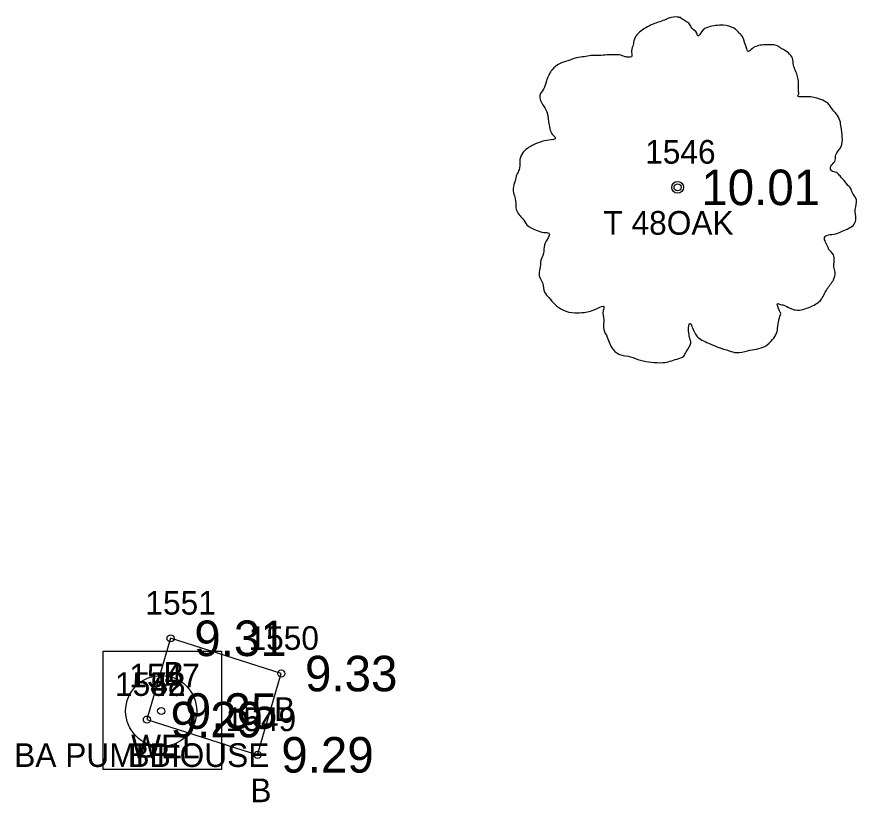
# Model space of a CAD drawing. Extents: x 2608598 to 2610682, y 641451 to 643526.
# Drawn here: x 2609098.39 to 2609133.87, y 643248.82 to 643281.98 of the extents above; entities that cross this region are included whole.
import ezdxf

# ---------------------------------------------------------------- set-up
doc = ezdxf.new("R2010")
doc.units = 0
for name, color, linetype in [('RD_EX_Bldg', 7, 'Continuous'), ('RD_EX_Bldg_txCode', 7, 'Continuous'), ('RD_EX_BldgApp_txCode', 7, 'Continuous'), ('RD_EX_SU_H2O', 7, 'Continuous'), ('RD_EX_TX_Bldg_ELEV', 7, 'Continuous'), ('RD_EX_TX_BldgApp_ELEV', 7, 'Continuous'), ('RD_EX_TX_VEG_ELEV', 7, 'Continuous'), ('RD_EX_VEG', 7, 'Continuous'), ('RD_EX_VEG_txCode', 7, 'Continuous'), ('RD_SMD_Locator', 7, 'Continuous')]:
    doc.layers.add(name, color=color, linetype=linetype)

msp = doc.modelspace()

# ---------------------------------------------------------------- linework, layer by layer
at = {"layer": 'RD_EX_Bldg'}
msp.add_lwpolyline([(2609103.878, 643252.305), (2609108.553, 643250.817), (2609109.553, 643254.249), (2609104.878, 643255.737), (2609103.878, 643252.305)], dxfattribs=at)
at = {"layer": 'RD_EX_BldgApp_txCode'}
msp.add_circle((2609104.482, 643252.665), 0.15, dxfattribs=at)
at = {"layer": 'RD_EX_SU_H2O'}
msp.add_lwpolyline([(2609102.029, 643250.193), (2609102.029, 643255.193), (2609107.029, 643255.193), (2609107.029, 643250.193)], close=True, dxfattribs=at)
msp.add_circle((2609104.482, 643252.665), 1.5, dxfattribs=at)
at = {"layer": 'RD_EX_VEG'}
for centre, radius in [((2609126.286, 643274.778), 0.25), ((2609126.273, 643274.759), 0.0001)]:
    msp.add_circle(centre, radius, dxfattribs=at)
for points in [[(2609126.418, 643281.945), (2609126.118, 643281.97), (2609125.793, 643281.87), (2609125.543, 643281.77), (2609125.318, 643281.695), (2609125.094, 643281.595), (2609124.794, 643281.42), (2609124.569, 643281.22), (2609124.444, 643280.97), (2609124.394, 643280.745), (2609124.344, 643280.471), (2609124.344, 643280.296), (2609124.219, 643280.271), (2609124.069, 643280.296), (2609123.819, 643280.371), (2609123.569, 643280.371), (2609123.319, 643280.371), (2609122.969, 643280.346), (2609122.62, 643280.346), (2609122.345, 643280.296), (2609122.02, 643280.246), (2609121.645, 643280.121), (2609121.295, 643279.996), (2609120.995, 643279.746), (2609120.745, 643279.271), (2609120.62, 643278.921), (2609120.471, 643278.671), (2609120.62, 643278.222), (2609120.795, 643277.872), (2609120.82, 643277.672), (2609120.895, 643277.247), (2609120.995, 643277.022), (2609121.12, 643276.822), (2609121.045, 643276.797), (2609120.67, 643276.747), (2609120.371, 643276.647), (2609119.946, 643276.422), (2609119.721, 643276.197), (2609119.621, 643275.872), (2609119.596, 643275.523), (2609119.496, 643275.323), (2609119.421, 643275.048), (2609119.396, 643274.973), (2609119.346, 643274.648), (2609119.446, 643274.198), (2609119.471, 643273.848), (2609119.596, 643273.623), (2609119.746, 643273.449), (2609119.921, 643273.199), (2609120.321, 643272.974), (2609120.645, 643272.874), (2609120.845, 643272.849), (2609120.67, 643272.349), (2609120.62, 643271.999), (2609120.496, 643271.599), (2609120.496, 643271.524), (2609120.446, 643271.05), (2609120.595, 643270.725), (2609120.67, 643270.35), (2609120.845, 643270.125), (2609121.12, 643269.825), (2609121.445, 643269.6), (2609121.945, 643269.475), (2609122.345, 643269.5), (2609122.92, 643269.675), (2609123.169, 643269.75), (2609123.144, 643269.575), (2609123.169, 643269.2), (2609123.169, 643268.776), (2609123.319, 643268.451), (2609123.419, 643268.176), (2609123.569, 643267.926), (2609123.894, 643267.701), (2609124.294, 643267.626), (2609124.719, 643267.476), (2609125.169, 643267.401), (2609125.668, 643267.376), (2609126.268, 643267.526), (2609126.543, 643267.651), (2609126.643, 643267.826), (2609126.843, 643268.201), (2609126.793, 643268.426), (2609126.818, 643269.026), (2609126.918, 643268.851), (2609127.093, 643268.501), (2609127.592, 643268.201), (2609127.992, 643268.026), (2609128.467, 643267.876), (2609128.767, 643267.801), (2609129.242, 643267.876), (2609129.617, 643267.951), (2609129.991, 643268.076), (2609130.291, 643268.351), (2609130.466, 643268.626), (2609130.516, 643268.901), (2609130.591, 643269.275), (2609130.641, 643269.45)], [(2609130.641, 643269.45), (2609130.566, 643269.625), (2609130.516, 643269.875), (2609130.591, 643269.85), (2609130.766, 643269.8), (2609131.041, 643269.675), (2609131.266, 643269.6), (2609131.591, 643269.625), (2609131.866, 643269.725), (2609132.315, 643270), (2609132.59, 643270.475), (2609132.865, 643270.875), (2609132.94, 643271.2), (2609132.89, 643271.424), (2609132.865, 643271.924), (2609132.665, 643272.174), (2609132.615, 643272.299), (2609132.515, 643272.699), (2609132.59, 643272.749), (2609132.865, 643272.799), (2609133.24, 643272.924), (2609133.515, 643273.049), (2609133.74, 643273.224), (2609133.815, 643273.449), (2609133.79, 643273.848), (2609133.84, 643274.248), (2609133.765, 643274.398), (2609133.665, 643274.548), (2609133.59, 643274.748), (2609133.44, 643274.898), (2609133.34, 643275.048), (2609133.24, 643275.148), (2609133.115, 643275.298), (2609132.94, 643275.423), (2609132.79, 643275.473), (2609132.74, 643275.623), (2609132.89, 643275.823), (2609132.94, 643275.922), (2609132.965, 643276.147), (2609133.19, 643276.497), (2609133.24, 643276.897), (2609133.19, 643277.322), (2609133.14, 643277.597), (2609132.99, 643277.872), (2609132.79, 643278.122), (2609132.665, 643278.296), (2609132.49, 643278.421), (2609132.165, 643278.546), (2609131.916, 643278.596), (2609131.566, 643278.596), (2609131.366, 643278.646), (2609131.391, 643278.696), (2609131.391, 643278.846), (2609131.391, 643279.121), (2609131.316, 643279.571), (2609131.166, 643280.071), (2609131.166, 643280.096), (2609131.066, 643280.346), (2609130.841, 643280.545), (2609130.666, 643280.645), (2609130.466, 643280.77), (2609130.216, 643280.795), (2609129.916, 643280.795), (2609129.642, 643280.745), (2609129.442, 643280.645), (2609129.267, 643280.52), (2609129.192, 643280.67), (2609129.092, 643280.97), (2609129.042, 643281.12), (2609128.892, 643281.295), (2609128.667, 643281.495), (2609128.217, 643281.62), (2609127.592, 643281.545), (2609127.293, 643281.345), (2609127.143, 643281.17), (2609127.093, 643281.295), (2609126.893, 643281.495), (2609126.793, 643281.67), (2609126.618, 643281.795), (2609126.468, 643281.895), (2609126.368, 643281.945)]]:
    msp.add_spline(points, degree=3, dxfattribs=at)
at = {"layer": 'RD_SMD_Locator'}
for centre in [(2609126.286, 643274.778), (2609104.878, 643255.737), (2609109.553, 643254.249), (2609103.878, 643252.305), (2609103.878, 643252.305), (2609108.553, 643250.817)]:
    msp.add_circle(centre, 0.15, dxfattribs=at)

# ---------------------------------------------------------------- texts
at = {"layer": 'RD_EX_Bldg_txCode'}
for s, p in [('1551', (2609103.815, 643256.737)), ('1550', (2609108.167, 643255.249)), ('B', (2609104.571, 643253.737)), ('1548', (2609102.532, 643253.305)), ('1552', (2609102.532, 643253.305)), ('B', (2609109.246, 643252.249)), ('1549', (2609107.206, 643251.817)), ('BA PUMPHOUSE', (2609098.276, 643250.305)), ('BB', (2609103.099, 643250.305)), ('B', (2609108.246, 643248.817))]:
    msp.add_text(s, height=1, dxfattribs=at).set_placement(p)
at = {"layer": 'RD_EX_BldgApp_txCode'}
for s, p in [('1547', (2609103.136, 643253.665)), ('WEL', (2609103.214, 643250.665))]:
    msp.add_text(s, height=1, dxfattribs=at).set_placement(p)
at = {"layer": 'RD_EX_TX_Bldg_ELEV'}
for s, p in [('9.31', (2609105.878, 643254.987)), ('9.33', (2609110.553, 643253.499)), ('9.29', (2609104.878, 643251.555)), ('9.29', (2609104.878, 643251.555)), ('9.29', (2609109.553, 643250.067))]:
    msp.add_text(s, height=1.5, dxfattribs=at).set_placement(p)
at = {"layer": 'RD_EX_TX_BldgApp_ELEV'}
msp.add_text('9.35', height=1.5, dxfattribs=at).set_placement((2609105.482, 643251.915))
at = {"layer": 'RD_EX_TX_VEG_ELEV'}
msp.add_text('10.01', height=1.5, dxfattribs=at).set_placement((2609127.286, 643274.028))
at = {"layer": 'RD_EX_VEG_txCode'}
for s, p in [('1546', (2609124.916, 643275.778)), ('T 48OAK', (2609123.152, 643272.778))]:
    msp.add_text(s, height=1, dxfattribs=at).set_placement(p)

doc.saveas('drawing.dxf')
